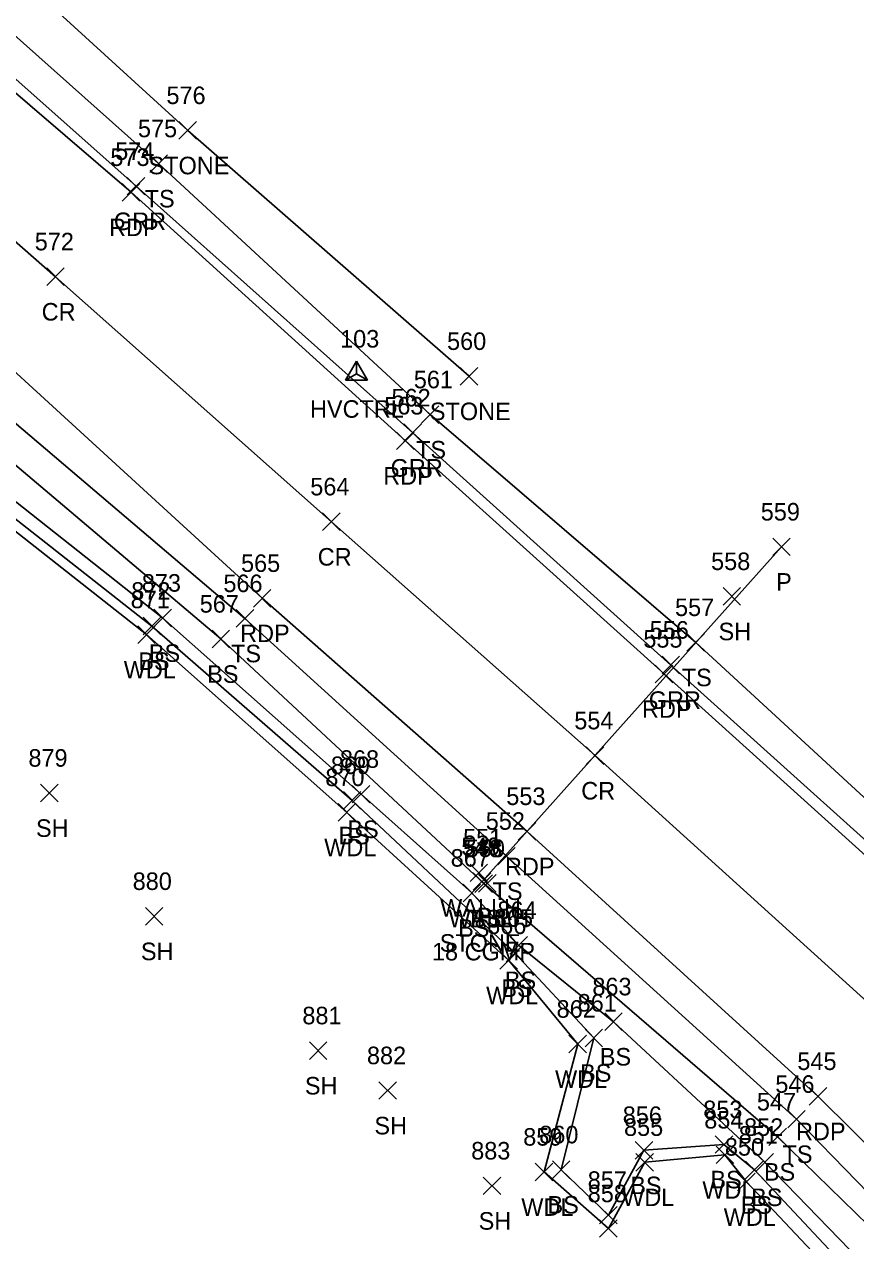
# Model space of a CAD drawing. Extents: x 1879695 to 1880991, y 836466 to 845172.
# Drawn here: x 1880089.2 to 1880183.9, y 844083.5 to 844222.2 of the extents above; entities that cross this region are included whole.
import ezdxf

# ---------------------------------------------------------------- set-up
doc = ezdxf.new("R2010")
doc.units = 0
for name, color, linetype in [('C_A', 7, 'Continuous'), ('C_I', 7, 'Continuous'), ('CPSM', 7, 'Continuous'), ('D_A', 7, 'Continuous'), ('D_C', 7, 'Continuous'), ('D_I', 7, 'Continuous'), ('D_TIC', 7, 'Continuous'), ('DCP', 7, 'Continuous'), ('DHW', 7, 'Continuous'), ('L_A', 7, 'Continuous'), ('L_I', 7, 'Continuous'), ('L_TIC', 7, 'Continuous'), ('LASF', 7, 'Continuous'), ('LAWA', 7, 'Continuous'), ('LELB', 7, 'Continuous'), ('P_A', 7, 'Continuous'), ('P_I', 7, 'Continuous'), ('P_TIC', 7, 'Continuous'), ('PET', 7, 'Continuous'), ('PRC', 7, 'Continuous'), ('R_A', 7, 'Continuous'), ('R_I', 7, 'Continuous'), ('R_TIC', 7, 'Continuous'), ('RGR', 7, 'Continuous')]:
    doc.layers.add(name, color=color, linetype=linetype)

msp = doc.modelspace()

# ---------------------------------------------------------------- linework, layer by layer
at = {"layer": 'CPSM'}
for p, q in [((1880125.8, 844181.6), (1880127.05, 844183.77)), ((1880128.3, 844181.6), (1880127.05, 844183.77)), ((1880127.05, 844182.33), (1880127.05, 844183.77)), ((1880125.8, 844181.6), (1880127.05, 844182.33)), ((1880125.8, 844181.6), (1880128.3, 844181.6)), ((1880127.05, 844182.33), (1880127.05, 844182.33)), ((1880127.05, 844182.33), (1880128.3, 844181.6))]:
    msp.add_line(p, q, dxfattribs=at)
at = {"layer": 'D_TIC'}
for points in [[(1880174.49, 844161.62), (1880176.49, 844163.62)], [(1880176.49, 844161.62), (1880174.49, 844163.62)], [(1880139.99, 844124.47), (1880141.99, 844126.47)], [(1880141.99, 844124.47), (1880139.99, 844126.47)], [(1880140.36, 844123.48), (1880142.36, 844125.48)], [(1880142.36, 844123.48), (1880140.36, 844125.48)], [(1880140.95, 844123.26), (1880142.95, 844125.26)], [(1880142.95, 844123.26), (1880140.95, 844125.26)]]:
    msp.add_lwpolyline(points, dxfattribs=at)
at = {"layer": 'DCP'}
msp.add_lwpolyline([(1880141.36, 844124.48), (1880175.49, 844162.62)], dxfattribs=at)
at = {"layer": 'DHW'}
msp.add_lwpolyline([(1880141.95, 844124.26), (1880140.99, 844125.47)], dxfattribs=at)
at = {"layer": 'L_TIC'}
for points in [[(1880106.81, 844209.08), (1880108.81, 844211.08)], [(1880108.81, 844209.08), (1880106.81, 844211.08)], [(1880103.5, 844205.3), (1880105.5, 844207.3)], [(1880105.5, 844205.3), (1880103.5, 844207.3)], [(1880138.87, 844181.06), (1880140.87, 844183.06)], [(1880140.87, 844181.06), (1880138.87, 844183.06)], [(1880134.43, 844176.69), (1880136.43, 844178.69)], [(1880136.43, 844176.69), (1880134.43, 844178.69)], [(1880168.83, 844155.97), (1880170.83, 844157.97)], [(1880170.83, 844155.97), (1880168.83, 844157.97)], [(1880103.95, 844153.51), (1880105.95, 844155.51)], [(1880105.95, 844153.51), (1880103.95, 844155.51)], [(1880113.34, 844153.46), (1880115.34, 844155.46)], [(1880115.34, 844153.46), (1880113.34, 844155.46)], [(1880102.11, 844151.62), (1880104.11, 844153.62)], [(1880104.11, 844151.62), (1880102.11, 844153.62)], [(1880102.74, 844152.59), (1880104.74, 844154.59)], [(1880104.74, 844152.59), (1880102.74, 844154.59)], [(1880110.59, 844151.12), (1880112.59, 844153.12)], [(1880112.59, 844151.12), (1880110.59, 844153.12)], [(1880164.71, 844150.73), (1880166.71, 844152.73)], [(1880166.71, 844150.73), (1880164.71, 844152.73)], [(1880091.03, 844133.56), (1880093.03, 844135.56)], [(1880093.03, 844133.56), (1880091.03, 844135.56)], [(1880126.57, 844133.43), (1880128.57, 844135.43)], [(1880128.57, 844133.43), (1880126.57, 844135.43)], [(1880125.55, 844132.72), (1880127.55, 844134.72)], [(1880127.55, 844132.72), (1880125.55, 844134.72)], [(1880124.95, 844131.35), (1880126.95, 844133.35)], [(1880126.95, 844131.35), (1880124.95, 844133.35)], [(1880143.15, 844126.37), (1880145.15, 844128.37)], [(1880145.15, 844126.37), (1880143.15, 844128.37)], [(1880140.55, 844123.24), (1880142.55, 844125.24)], [(1880142.55, 844123.24), (1880140.55, 844125.24)], [(1880139.19, 844122.17), (1880141.19, 844124.17)], [(1880141.19, 844122.17), (1880139.19, 844124.17)], [(1880102.99, 844119.51), (1880104.99, 844121.51)], [(1880104.99, 844119.51), (1880102.99, 844121.51)], [(1880144.52, 844116.21), (1880146.52, 844118.21)], [(1880146.52, 844116.21), (1880144.52, 844118.21)], [(1880143.4, 844114.49), (1880145.4, 844116.49)], [(1880145.4, 844114.49), (1880143.4, 844116.49)], [(1880144.11, 844115.32), (1880146.11, 844117.32)], [(1880146.11, 844115.32), (1880144.11, 844117.32)], [(1880155.34, 844107.5), (1880157.34, 844109.5)], [(1880157.34, 844107.5), (1880155.34, 844109.5)], [(1880151.26, 844104.95), (1880153.26, 844106.95)], [(1880153.26, 844104.95), (1880151.26, 844106.95)], [(1880153.09, 844105.65), (1880155.09, 844107.65)], [(1880155.09, 844105.65), (1880153.09, 844107.65)], [(1880121.68, 844104.2), (1880123.68, 844106.2)], [(1880123.68, 844104.2), (1880121.68, 844106.2)], [(1880129.6, 844099.65), (1880131.6, 844101.65)], [(1880131.6, 844099.65), (1880129.6, 844101.65)], [(1880176.19, 844096.39), (1880178.19, 844098.39)], [(1880178.19, 844096.39), (1880176.19, 844098.39)], [(1880167.93, 844093.5), (1880169.93, 844095.5)], [(1880169.93, 844093.5), (1880167.93, 844095.5)], [(1880174.04, 844094.38), (1880176.04, 844096.38)], [(1880176.04, 844094.38), (1880174.04, 844096.38)], [(1880158.81, 844092.84), (1880160.81, 844094.84)], [(1880160.81, 844092.84), (1880158.81, 844094.84)], [(1880168.04, 844092.32), (1880170.04, 844094.32)], [(1880170.04, 844092.32), (1880168.04, 844094.32)], [(1880149.38, 844090.63), (1880151.38, 844092.63)], [(1880151.38, 844090.63), (1880149.38, 844092.63)], [(1880158.9, 844091.48), (1880160.9, 844093.48)], [(1880160.9, 844091.48), (1880158.9, 844093.48)], [(1880171.4, 844090.6), (1880173.4, 844092.6)], [(1880173.4, 844090.6), (1880171.4, 844092.6)], [(1880172.59, 844091.48), (1880174.59, 844093.48)], [(1880174.59, 844091.48), (1880172.59, 844093.48)], [(1880147.42, 844090.37), (1880149.42, 844092.37)], [(1880149.42, 844090.37), (1880147.42, 844092.37)], [(1880170.48, 844089.23), (1880172.48, 844091.23)], [(1880172.48, 844089.23), (1880170.48, 844091.23)], [(1880141.48, 844088.79), (1880143.48, 844090.79)], [(1880143.48, 844088.79), (1880141.48, 844090.79)], [(1880154.76, 844085.44), (1880156.76, 844087.44)], [(1880156.76, 844085.44), (1880154.76, 844087.44)], [(1880154.76, 844083.92), (1880156.76, 844085.92)], [(1880156.76, 844083.92), (1880154.76, 844085.92)]]:
    msp.add_lwpolyline(points, dxfattribs=at)
at = {"layer": 'LASF'}
msp.add_lwpolyline([(1880139.87, 844182.06), (1880107.81, 844210.08), (1880073.67, 844241.21), (1880039.73, 844270.44), (1880011.8, 844299.45), (1879985.05, 844328.99), (1879962.59, 844360.65), (1879939.31, 844397.46), (1879924.45, 844424.63), (1879917.02, 844424.23), (1879898.51, 844460.46), (1879892.86, 844475.33), (1879896.16, 844478.29), (1879889.96, 844497.62)], dxfattribs=at)
at = {"layer": 'LAWA'}
msp.add_lwpolyline([(1880235.36, 844016.97), (1880226.78, 844031.19), (1880215.51, 844044.03), (1880209.22, 844044.19), (1880209.6, 844049.55), (1880199.81, 844058.74), (1880190.2, 844070.4), (1880171.48, 844090.23), (1880169.04, 844093.32), (1880159.9, 844092.48), (1880155.76, 844084.92), (1880148.42, 844091.37), (1880152.26, 844105.95), (1880144.4, 844115.49), (1880125.95, 844132.35), (1880103.11, 844152.62), (1880080.73, 844170.23), (1880061.24, 844186.41), (1880031.89, 844196.39), (1880020.4, 844184.31), (1880005.38, 844176.44), (1879986.51, 844163.82)], dxfattribs=at)
at = {"layer": 'LELB'}
for points in [[(1880237.65, 844030.17), (1880225.55, 844045.25), (1880203.19, 844067.94), (1880175.04, 844095.38), (1880141.55, 844124.24), (1880111.59, 844152.12), (1880079.67, 844179.09), (1880044.89, 844208.16), (1880013.5, 844237.54), (1880003.34, 844247.82), (1879979.16, 844270.62), (1879948.51, 844300.87), (1879928.97, 844335.67), (1879901.59, 844373.87), (1879881.39, 844405.75), (1879863.37, 844445.07), (1879846.41, 844479.41), (1879833.35, 844517.23), (1879821, 844560.9), (1879811.24, 844600.26), (1879800.64, 844646.71), (1879794.2, 844680.16), (1879792.03, 844683.6), (1879789.08, 844683.63)], [(1880243.53, 844023.94), (1880226.64, 844046.28), (1880204.68, 844069.12), (1880177.19, 844097.39), (1880144.15, 844127.37), (1880114.34, 844154.46), (1880082.65, 844181.38), (1880047.53, 844211.78), (1880015.32, 844240.12), (1879982.29, 844271.84), (1879951.96, 844303.04), (1879930.28, 844336.91), (1879904.08, 844374.32), (1879883.92, 844406.9), (1879866.98, 844446.02), (1879852.23, 844482.49), (1879838.68, 844519.35), (1879826.86, 844562.48), (1879815.22, 844600.52)], [(1880274.18, 844042.18), (1880252.69, 844068.34), (1880228.42, 844092.99), (1880199.77, 844120.37), (1880165.71, 844151.73), (1880135.43, 844177.69), (1880104.5, 844206.3), (1880070.17, 844236.88), (1880037.83, 844267.79), (1880007.31, 844296.06), (1879981.71, 844326.11), (1879957.94, 844357.83), (1879934.98, 844394.4), (1879917.02, 844424.23)], [(1880208.14, 844057.06), (1880205.3, 844059.71), (1880199.4, 844059.75), (1880191.54, 844071.18), (1880172.4, 844091.6), (1880168.93, 844094.5), (1880159.81, 844093.84), (1880155.76, 844086.44), (1880150.38, 844091.63), (1880154.09, 844106.65), (1880145.11, 844116.32), (1880126.55, 844133.72), (1880103.74, 844153.59), (1880081.3, 844171.15), (1880062.9, 844187.7), (1880046.08, 844200.5), (1880030.27, 844215.53), (1880015.96, 844231.11), (1880002.51, 844242.73), (1879985.64, 844257.52)], [(1880223.61, 844044.33), (1880209.51, 844057.91), (1880192.94, 844072.51), (1880173.59, 844092.48), (1880156.34, 844108.5), (1880145.52, 844117.21), (1880140.19, 844123.17), (1880127.57, 844134.43), (1880104.95, 844154.51), (1880082.15, 844172.53), (1880063.54, 844188.27), (1880047.18, 844201.5), (1880031.58, 844216.92), (1880015.96, 844231.11)]]:
    msp.add_lwpolyline(points, dxfattribs=at)
at = {"layer": 'P_TIC'}
for points in [[(1880100.36, 844202.03), (1880102.36, 844204.03)], [(1880102.36, 844202.03), (1880100.36, 844204.03)], [(1880091.74, 844192.41), (1880093.74, 844194.41)], [(1880093.74, 844192.41), (1880091.74, 844194.41)], [(1880131.62, 844173.7), (1880133.62, 844175.7)], [(1880133.62, 844173.7), (1880131.62, 844175.7)], [(1880123.19, 844164.48), (1880125.19, 844166.48)], [(1880125.19, 844164.48), (1880123.19, 844166.48)], [(1880115.3, 844155.76), (1880117.3, 844157.76)], [(1880117.3, 844155.76), (1880115.3, 844157.76)], [(1880161.1, 844147.13), (1880163.1, 844149.13)], [(1880163.1, 844147.13), (1880161.1, 844149.13)], [(1880153.23, 844137.82), (1880155.23, 844139.82)], [(1880155.23, 844137.82), (1880153.23, 844139.82)], [(1880145.48, 844129.19), (1880147.48, 844131.19)], [(1880147.48, 844129.19), (1880145.48, 844131.19)], [(1880178.65, 844098.99), (1880180.65, 844100.99)], [(1880180.65, 844098.99), (1880178.65, 844100.99)]]:
    msp.add_lwpolyline(points, dxfattribs=at)
at = {"layer": 'PET'}
for points in [[(1880269.75, 844039.67), (1880250.27, 844065.9), (1880225.97, 844090.31), (1880195.98, 844117.55), (1880162.1, 844148.13), (1880132.62, 844174.7), (1880101.36, 844203.03), (1880066.94, 844232.59), (1880034.5, 844263.16), (1880004.09, 844293.64), (1879978.17, 844323.39), (1879954.46, 844354.82), (1879930.76, 844391.37), (1879912.37, 844423.12), (1879894.17, 844458.9), (1879879.41, 844492.34), (1879865.46, 844529.81), (1879852.88, 844569.32), (1879843.17, 844608.03)], [(1880246.17, 844024.86), (1880229.35, 844048.54), (1880207.67, 844072.23), (1880179.65, 844099.99), (1880146.48, 844130.19), (1880116.3, 844156.76), (1880085.61, 844184.86), (1880050.42, 844215.32), (1880017.65, 844245.83), (1879986.99, 844277.13), (1879959.04, 844308.59), (1879934.2, 844340.79), (1879910.26, 844378.73), (1879891.14, 844411.43), (1879872.36, 844448.44), (1879856.33, 844484.43), (1879842.37, 844521.56), (1879829.6, 844563.28), (1879820.43, 844602.23)]]:
    msp.add_lwpolyline(points, dxfattribs=at)
at = {"layer": 'PRC'}
msp.add_lwpolyline([(1880256.85, 844032.04), (1880238.91, 844056.2), (1880216.7, 844080.65), (1880187.27, 844108.93), (1880154.23, 844138.82), (1880124.19, 844165.48), (1880092.74, 844193.41), (1880058.56, 844223.39), (1880025.99, 844253.92), (1879995.14, 844285.41), (1879968.79, 844316.24), (1879945.09, 844347.91), (1879920.67, 844385.19), (1879902.45, 844417.14), (1879883.72, 844454.21), (1879868.53, 844488.38), (1879854.47, 844526.01), (1879841.81, 844566.38), (1879832.13, 844605)], dxfattribs=at)
at = {"layer": 'R_TIC'}
for points in [[(1880100.92, 844202.72), (1880102.92, 844204.72)], [(1880102.92, 844202.72), (1880100.92, 844204.72)], [(1880132.45, 844174.62), (1880134.45, 844176.62)], [(1880134.45, 844174.62), (1880132.45, 844176.62)], [(1880161.87, 844148.15), (1880163.87, 844150.15)], [(1880163.87, 844148.15), (1880161.87, 844150.15)]]:
    msp.add_lwpolyline(points, dxfattribs=at)
at = {"layer": 'RGR'}
msp.add_lwpolyline([(1880270.9, 844040.93), (1880251.09, 844066.69), (1880226.93, 844091.38), (1880197.34, 844118.12), (1880162.87, 844149.15), (1880133.45, 844175.62), (1880101.92, 844203.72), (1880067.67, 844234.21), (1880035.3, 844264.37), (1880005.3, 844294.8), (1879979.45, 844324.37), (1879956.29, 844356.24), (1879932.57, 844392.56), (1879914.54, 844423.96), (1879896.38, 844459.86), (1879881.66, 844493.03), (1879867.6, 844530.61), (1879855.21, 844570.01), (1879845.36, 844608.98)], dxfattribs=at)

# ---------------------------------------------------------------- texts
at = {"layer": 'C_A'}
msp.add_text('HVCTRL', height=2, dxfattribs=at).set_placement((1880121.75, 844177.33))
at = {"layer": 'C_I'}
msp.add_text('103', height=2, dxfattribs=at).set_placement((1880125.18, 844185.33))
at = {"layer": 'D_A'}
for s, p in [('P', (1880174.87, 844157.62)), ('WALLH', (1880136.58, 844120.47)), ('WALLH', (1880137.54, 844119.26)), ('P', (1880140.74, 844119.48))]:
    msp.add_text(s, height=2, dxfattribs=at).set_placement(p)
at = {"layer": 'D_C'}
for s, p in [('18 CGMP', (1880135.65, 844115.48)), ('STONE', (1880136.53, 844116.47))]:
    msp.add_text(s, height=2, dxfattribs=at).set_placement(p)
at = {"layer": 'D_I'}
for s, p in [('559', (1880173.12, 844165.62)), ('551', (1880139.2, 844128.47)), ('549', (1880138.99, 844127.48)), ('550', (1880139.5, 844127.26))]:
    msp.add_text(s, height=2, dxfattribs=at).set_placement(p)
at = {"layer": 'L_A'}
for s, p in [('STONE', (1880103.35, 844205.08)), ('TS', (1880102.91, 844201.3)), ('STONE', (1880135.41, 844177.06)), ('TS', (1880133.84, 844172.69)), ('SH', (1880168.31, 844151.97)), ('BS', (1880103.39, 844149.51)), ('TS', (1880112.75, 844149.46)), ('WDL', (1880100.52, 844147.62)), ('BS', (1880102.18, 844148.59)), ('BS', (1880110.03, 844147.12)), ('TS', (1880164.12, 844146.73)), ('SH', (1880090.52, 844129.56)), ('BS', (1880126.01, 844129.43)), ('BS', (1880124.99, 844128.72)), ('WDL', (1880123.37, 844127.35)), ('TS', (1880142.56, 844122.37)), ('BS', (1880138.63, 844118.17)), ('BS', (1880139.99, 844119.24)), ('SH', (1880102.48, 844115.51)), ('BS', (1880143.55, 844111.32)), ('BS', (1880143.96, 844112.21)), ('WDL', (1880141.82, 844110.49)), ('BS', (1880154.78, 844103.5)), ('BS', (1880152.53, 844101.65)), ('SH', (1880121.17, 844100.2)), ('WDL', (1880149.68, 844100.95)), ('SH', (1880129.09, 844095.65)), ('TS', (1880175.6, 844092.39)), ('BS', (1880167.38, 844089.5)), ('BS', (1880173.48, 844090.38)), ('BS', (1880158.25, 844088.84)), ('WDL', (1880166.46, 844088.32)), ('WDL', (1880145.83, 844086.37)), ('BS', (1880148.82, 844086.63)), ('WDL', (1880157.32, 844087.48)), ('BS', (1880170.84, 844086.6)), ('BS', (1880172.03, 844087.48)), ('WDL', (1880168.9, 844085.23)), ('SH', (1880140.97, 844084.79))]:
    msp.add_text(s, height=2, dxfattribs=at).set_placement(p)
at = {"layer": 'L_I'}
for s, p in [('576', (1880105.39, 844213.08)), ('575', (1880102.14, 844209.3)), ('560', (1880137.37, 844185.06)), ('561', (1880133.58, 844180.69)), ('558', (1880167.46, 844159.97)), ('873', (1880102.58, 844157.51)), ('566', (1880111.88, 844157.46)), ('871', (1880101.31, 844155.62)), ('872', (1880101.38, 844156.59)), ('567', (1880109.18, 844155.12)), ('557', (1880163.35, 844154.73)), ('879', (1880089.66, 844137.56)), ('869', (1880124.13, 844136.72)), ('868', (1880125.16, 844137.43)), ('870', (1880123.5, 844135.35)), ('552', (1880141.78, 844130.37)), ('548', (1880139.19, 844127.24)), ('867', (1880137.78, 844126.17)), ('880', (1880101.54, 844123.51)), ('864', (1880143.11, 844120.21)), ('866', (1880141.94, 844118.49)), ('865', (1880142.7, 844119.32)), ('863', (1880153.93, 844111.5)), ('862', (1880149.85, 844108.95)), ('861', (1880152.25, 844109.65)), ('881', (1880120.88, 844108.2)), ('882', (1880128.24, 844103.65)), ('546', (1880174.78, 844100.39)), ('853', (1880166.57, 844097.5)), ('547', (1880172.68, 844098.38)), ('856', (1880157.39, 844096.84)), ('854', (1880166.68, 844096.32)), ('860', (1880147.88, 844094.63)), ('855', (1880157.54, 844095.48)), ('851', (1880170.61, 844094.6)), ('852', (1880171.22, 844095.48)), ('859', (1880146.05, 844094.37)), ('850', (1880169.03, 844093.23)), ('883', (1880140.12, 844092.79)), ('857', (1880153.4, 844089.44)), ('858', (1880153.4, 844087.92))]:
    msp.add_text(s, height=2, dxfattribs=at).set_placement(p)
at = {"layer": 'P_A'}
for s, p in [('RDP', (1880098.85, 844198.03)), ('CR', (1880091.17, 844188.41)), ('RDP', (1880130.1, 844169.7)), ('CR', (1880122.63, 844160.48)), ('RDP', (1880113.79, 844151.76)), ('RDP', (1880159.59, 844143.13)), ('CR', (1880152.66, 844133.82)), ('RDP', (1880143.97, 844125.19)), ('RDP', (1880177.14, 844094.99))]:
    msp.add_text(s, height=2, dxfattribs=at).set_placement(p)
at = {"layer": 'P_I'}
for s, p in [('573', (1880099, 844206.03)), ('572', (1880090.38, 844196.41)), ('563', (1880130.21, 844177.7)), ('564', (1880121.78, 844168.48)), ('565', (1880113.89, 844159.76)), ('555', (1880159.74, 844151.13)), ('554', (1880151.87, 844141.82)), ('553', (1880144.12, 844133.19)), ('545', (1880177.29, 844102.99))]:
    msp.add_text(s, height=2, dxfattribs=at).set_placement(p)
at = {"layer": 'R_A'}
for p in [(1880099.4, 844198.72), (1880130.94, 844170.62), (1880160.36, 844144.15)]:
    msp.add_text('GRR', height=2, dxfattribs=at).set_placement(p)
at = {"layer": 'R_I'}
for s, p in [('574', (1880099.55, 844206.72)), ('562', (1880131.04, 844178.62)), ('556', (1880160.46, 844152.15))]:
    msp.add_text(s, height=2, dxfattribs=at).set_placement(p)

doc.saveas('drawing.dxf')
